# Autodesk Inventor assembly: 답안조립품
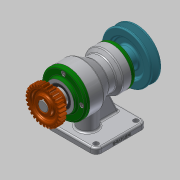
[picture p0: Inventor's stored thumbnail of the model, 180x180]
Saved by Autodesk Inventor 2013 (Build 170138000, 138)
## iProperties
Created: 2019-01
Part Number: 답안조립품
Document SubType Name: Assembly
Designer: dgall
Author: dgall
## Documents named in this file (15)
- C:\Users\dgall\Desktop\490107V1053\답안조립품.iam
- C:\Users\dgall\Desktop\490107V1053\본체.ipt
- C:\Users\dgall\Desktop\490107V1053\V-벨트풀리.ipt
- C:\Users\dgall\Desktop\490107V1053\뒤커버.ipt
- C:\Users\dgall\Desktop\490107V1053\멈춤나사 M3.ipt
- C:\Users\dgall\Desktop\490107V1053\베어링 6203.ipt
- C:\Users\dgall\Desktop\490107V1053\베어링 6205.ipt
- C:\Users\dgall\Desktop\490107V1053\볼트 M4.ipt
- C:\Users\dgall\Desktop\490107V1053\스퍼기어.ipt
- C:\Users\dgall\Desktop\490107V1053\앞커버.ipt
- C:\Users\dgall\Desktop\490107V1053\오일 실 17 30 8.ipt
- C:\Users\dgall\Desktop\490107V1053\오일 실 25 38 8.ipt
- C:\Users\dgall\Desktop\490107V1053\축.ipt
- C:\Users\dgall\Desktop\490107V1053\키 5 x 5 x 20.ipt
- C:\Users\dgall\Desktop\490107V1053\키 6 x 6 x 18.ipt
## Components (1 placed, 1 different names)
1. V-벨트풀리:1 — 각도:4
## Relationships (1: Angle 1)
- 각도:4 [Angle]: V-벨트풀리:1
